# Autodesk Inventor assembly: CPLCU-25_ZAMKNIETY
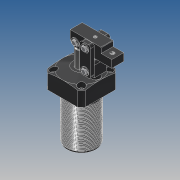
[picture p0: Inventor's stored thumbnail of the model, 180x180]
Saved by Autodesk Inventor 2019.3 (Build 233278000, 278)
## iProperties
Created: 2010-03
Part Number: CPLCU-25_ZAMKNIETY
Material: Ogólny
Document SubType Name: Assembly
Designer: CADENGINEERING4
Sending System: PRO/ENGINEER BY PARAMETRIC TECHNOLOGY CORPORATION, 2007170
Preprocessor: PRO/ENGINEER BY PARAMETRIC TECHNOLOGY CORPORATION, 2007170
Title: CPLCU-25_ASM
Author: Administrator
Revision Number: 1LAST_VERSION
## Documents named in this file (10)
- E:\SERWER_ZAPAS\MODELE brakujace\PNEUMATIC\CPLCU(STEP)\cplcu-25_asm\CPLCU-25_ZAMKNIETY.iam
- E:\SERWER_ZAPAS\MODELE brakujace\PNEUMATIC\CPLCU(STEP)\cplcu-25_asm\CPLCU-25-07.ipt
- E:\SERWER_ZAPAS\MODELE brakujace\PNEUMATIC\CPLCU(STEP)\cplcu-25_asm\CPLCU-25-06.ipt
- E:\SERWER_ZAPAS\MODELE brakujace\PNEUMATIC\CPLCU(STEP)\cplcu-25_asm\CPLCU-25-01.ipt
- E:\SERWER_ZAPAS\MODELE brakujace\PNEUMATIC\CPLCU(STEP)\cplcu-25_asm\CPLCU-25-05.ipt
- E:\SERWER_ZAPAS\MODELE brakujace\PNEUMATIC\CPLCU(STEP)\cplcu-25_asm\CPLCU-25-02.ipt
- E:\SERWER_ZAPAS\MODELE brakujace\PNEUMATIC\CPLCU(STEP)\cplcu-25_asm\CPLCU-25-09.ipt
- E:\SERWER_ZAPAS\MODELE brakujace\PNEUMATIC\CPLCU(STEP)\cplcu-25_asm\CPLCU-25-03.ipt
- E:\SERWER_ZAPAS\MODELE brakujace\PNEUMATIC\CPLCU(STEP)\cplcu-25_asm\CPLCU-25-04.ipt
- E:\SERWER_ZAPAS\MODELE brakujace\PNEUMATIC\CPLCU(STEP)\cplcu-25_asm\LHC01D-32-01.ipt
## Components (21 placed, 21 different names)
1. CPLCU-25-07_0 — Zestawiające:17
2. CPLCU-25-06_1 — Zestawiające:1, Równoległe:1, Zestawiające:4, Zestawiające:5, Zestawiające:7, Zestawiające:17
3. CPLCU-25-01_2 — Zestawiające:6, Zestawiające:7, Zestawiające:10, Zestawiające:11, Zestawiające:12, Zestawiające:16, Zestawiające:20, Kątowe:1
4. CPLCU-25-05_3 — Zestawiające:25, Zestawiające:26, Zestawiające:28, Zestawiające:29, Kątowe:1
5. CPLCU-25-02_4 — Zestawiające:12, Zestawiające:13, Równoległe:2, Zestawiające:19, Zestawiające:24
6. CPLCU-25-02_5 — Zestawiające:14, Równoległe:3, Zestawiające:19, Zestawiające:20, Zestawiające:22, Zestawiające:26, Zestawiające:31
7. CPLCU-25-09_6 — Zestawiające:3, Zestawiające:4
8. CPLCU-25-09_7 — Zestawiające:13, Równoległe:2, Zestawiające:18
9. CPLCU-25-09_8 — Zestawiające:29, Zestawiające:30
10. CPLCU-25-09_9 — Zestawiające:27, Zestawiające:28, Zestawiające:31
11. CPLCU-25-09_10 — Zestawiające:14, Równoległe:3, Zestawiające:15
12. CPLCU-25-09_11 — Zestawiające:2, Zestawiające:5, Zestawiające:6
13. CPLCU-25-03_12 — Zestawiające:1, Równoległe:1, Zestawiające:2, Zestawiające:3, Zestawiające:8, Zestawiające:9
14. CPLCU-25-04_13 — Zestawiające:25, Równoległe:4, Zestawiające:27, Zestawiające:30
15. CPLCU-25-04_14 — Zestawiające:15, Zestawiające:16, Zestawiające:18, Zestawiające:21, Zestawiające:23, Równoległe:4, Równoległe:5
16. LHC01D-32-01_15 — Zestawiające:9, Zestawiające:10
17. LHC01D-32-01_16 — Zestawiające:8, Zestawiające:11
18. LHC01D-32-01_17 — Zestawiające:23, Zestawiające:24
19. LHC01D-32-01_18
20. LHC01D-32-01_19 — Zestawiające:21, Zestawiające:22, Równoległe:5
21. LHC01D-32-01_20
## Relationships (37: Mate 31, Flush 5, Angle 1)
- Zestawiające:1 [Mate]: CPLCU-25-06_1 ↔ CPLCU-25-03_12
- Równoległe:1 [Flush]: CPLCU-25-06_1 ↔ CPLCU-25-03_12
- Zestawiające:2 [Mate]: CPLCU-25-09_11 ↔ CPLCU-25-03_12
- Zestawiające:3 [Mate]: CPLCU-25-09_6 ↔ CPLCU-25-03_12
- Zestawiające:4 [Mate]: CPLCU-25-06_1 ↔ CPLCU-25-09_6
- Zestawiające:5 [Mate]: CPLCU-25-06_1 ↔ CPLCU-25-09_11
- Zestawiające:6 [Mate]: CPLCU-25-01_2 ↔ CPLCU-25-09_11
- Zestawiające:7 [Mate]: CPLCU-25-06_1 ↔ CPLCU-25-01_2
- Zestawiające:8 [Mate]: CPLCU-25-03_12 ↔ LHC01D-32-01_16
- Zestawiające:9 [Mate]: CPLCU-25-03_12 ↔ LHC01D-32-01_15
- Zestawiające:10 [Mate]: CPLCU-25-01_2 ↔ LHC01D-32-01_15
- Zestawiające:11 [Mate]: CPLCU-25-01_2 ↔ LHC01D-32-01_16
- Zestawiające:12 [Mate]: CPLCU-25-01_2 ↔ CPLCU-25-02_4
- Zestawiające:13 [Mate]: CPLCU-25-02_4 ↔ CPLCU-25-09_7
- Równoległe:2 [Flush]: CPLCU-25-02_4 ↔ CPLCU-25-09_7
- Zestawiające:14 [Mate]: CPLCU-25-02_5 ↔ CPLCU-25-09_10
- Równoległe:3 [Flush]: CPLCU-25-02_5 ↔ CPLCU-25-09_10
- Zestawiające:15 [Mate]: CPLCU-25-09_10 ↔ CPLCU-25-04_14
- Zestawiające:16 [Mate]: CPLCU-25-01_2 ↔ CPLCU-25-04_14
- Zestawiające:17 [Mate]: CPLCU-25-07_0 ↔ CPLCU-25-06_1
- Zestawiające:18 [Mate]: CPLCU-25-09_7 ↔ CPLCU-25-04_14
- Zestawiające:19 [Mate]: CPLCU-25-02_4 ↔ CPLCU-25-02_5
- Zestawiające:20 [Mate]: CPLCU-25-01_2 ↔ CPLCU-25-02_5
- Zestawiające:21 [Mate]: CPLCU-25-04_14 ↔ LHC01D-32-01_19
- Zestawiające:22 [Mate]: CPLCU-25-02_5 ↔ LHC01D-32-01_19
- Zestawiające:23 [Mate]: CPLCU-25-04_14 ↔ LHC01D-32-01_17
- Zestawiające:24 [Mate]: CPLCU-25-02_4 ↔ LHC01D-32-01_17
- Zestawiające:25 [Mate]: CPLCU-25-05_3 ↔ CPLCU-25-04_13
- Równoległe:4 [Flush]: CPLCU-25-04_13 ↔ CPLCU-25-04_14
- Zestawiające:26 [Mate]: CPLCU-25-05_3 ↔ CPLCU-25-02_5
- Zestawiające:27 [Mate]: CPLCU-25-09_9 ↔ CPLCU-25-04_13
- Zestawiające:28 [Mate]: CPLCU-25-05_3 ↔ CPLCU-25-09_9
- Zestawiające:29 [Mate]: CPLCU-25-05_3 ↔ CPLCU-25-09_8
- Zestawiające:30 [Mate]: CPLCU-25-09_8 ↔ CPLCU-25-04_13
- Zestawiające:31 [Mate]: CPLCU-25-02_5 ↔ CPLCU-25-09_9
- Kątowe:1 [Angle]: CPLCU-25-01_2 ↔ CPLCU-25-05_3
- Równoległe:5 [Flush]: CPLCU-25-04_14 ↔ LHC01D-32-01_19
